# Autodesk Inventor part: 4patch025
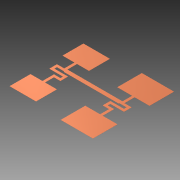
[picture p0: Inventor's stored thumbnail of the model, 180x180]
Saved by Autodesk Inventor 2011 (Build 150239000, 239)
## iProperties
Created: 2014-03
Part Number: 4patch025
Document SubType Name: Modeling
Designer: Evgeny
Density: 1 g/cm^3
Author: Evgeny
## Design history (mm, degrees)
sketch "Эскиз1"
  geometry: L1 (-64.5, 4.5)-(64.5, 4.5); L2 (64.5, -3)-(64.5, -4.5); L3 (64.5, -4.5)-(-64.5, -4.5); L4 (-64.5, -4.5)-(-64.5, -3); L5 (-70.5, 3)-(-72.9, 3); L6 (-81.5, -3)-(-64.5, -3); L7 (-70.5, 3)-(-70.5, 27); L8 (-64.5, 27)-(-64.5, 4.5); L9 (-72.9, 3)-(-87.5, 3); L10 (-87.5, 3)-(-87.5, -14); L11 (-81.5, -9)-(-81.5, -3); L12 (-81.5, -9)-(-49.5, -9); L13 (-49.5, -9)-(-49.5, -25); L14 (-55.5, -15)-(-87.5, -15); L15 (-87.5, -15)-(-87.5, -14); L16 (-55.5, -15)-(-55.5, -21); L17 (-49.5, -27)-(-49.5, -25); L18 (-49.5, -27)-(-64.5, -27); L19 (-70.5, -37)-(-70.5, -21); L20 (-70.5, -21)-(-55.5, -21); L21 (-70.5, -21)-(-57.4, -21); L22 (-64.5, -27)-(-64.5, -48); L23 (-70.5, -48)-(-70.5, -21); L24 (70.5, 3)-(87.5, 3); L25 (87.5, 3)-(87.5, -3); L26 (81.5, -3)-(64.5, -3); L27 (70.5, 3)-(70.5, 27); L28 (64.5, 27)-(64.5, 4.5); L29 (81.5, -3)-(81.5, -9); L30 (85.5, -15)-(87.5, -15); L31 (87.5, -15)-(87.5, -3); L32 (85.5, -15)-(55.5, -15); L33 (49.5, -15)-(49.5, -9); L34 (49.5, -9)-(81.5, -9); L35 (49.5, -9)-(55.5, -9); L36 (55.5, -15)-(55.5, -21); L37 (55.5, -27)-(49.5, -27); L38 (49.5, -27)-(49.5, -9); L39 (55.5, -27)-(64.5, -27); L40 (70.5, -27)-(70.5, -21); L41 (70.5, -21)-(55.5, -21); L42 (70.5, -21)-(65, -21); L43 (64.5, -27)-(64.5, -48); L44 (70.5, -48)-(70.5, -21); L45 (-98.5, 76)-(-36.5, 76); L46 (-36.5, 76)-(-36.5, 27); L47 (-98.5, 27)-(-98.5, 76); L48 (29.75, 84.5)-(105.25, 84.5); L49 (105.25, 84.5)-(105.25, 27); L50 (29.75, 27)-(29.75, 84.5); L51 (-98.5, -97)-(-36.5, -97); L52 (-36.5, -97)-(-36.5, -48); L53 (-98.5, -48)-(-98.5, -97); L54 (29.75, -105.5)-(105.25, -105.5); L55 (105.25, -105.5)-(105.25, -48); L56 (29.75, -48)-(29.75, -105.5); L57 (-36.5, 27)-(-64.5, 27); L58 (-70.5, 27)-(-98.5, 27); L59 (105.25, 27)-(70.5, 27); L60 (64.5, 27)-(29.75, 27); L61 (-36.5, -48)-(-64.5, -48); L62 (-70.5, -48)-(-98.5, -48); L63 (105.25, -48)-(70.5, -48); L64 (64.5, -48)-(29.75, -48); 1 further point
  constraints: 128 end point, 30 parallel, 15 horizontal, 14 perpendicular, 6 collinear
  dimensions: "d0" = 129 distance between parallel lines of L2 L4; "d1" = 64.5 distance from line of point (0, 0) L4; "d2" = 9 distance between parallel lines of L3 L1; "d3" = 4.5 distance from line of point (0, 0) L3; "d5" = 6 distance between parallel lines of L5 L6; "d7" = 6 distance between parallel lines of L7 L8; "d8" = 17 distance from line of L4.end L11; "d9" = 6 distance between parallel lines of L10 L11; "d10" = 6 distance between parallel lines of L12 L6; "d11" = 6 distance between parallel lines of L14 L12; "d12" = 15 distance between parallel lines of L17 L22; "d13" = 6 distance between parallel lines of L17 L16; "d14" = 6 distance between parallel lines of L18 L20; "d15" = 6 distance between parallel lines of L23 L22; "d18" = 64.5 distance from line of L22 point (0, 0); "d19" = 6 distance between parallel lines of L27 L28; "d20" = 17 distance between parallel lines of L29 L2; "d21" = 6 distance between parallel lines of L24 L26; "d22" = 6 distance between parallel lines of L31 L29; "d23" = 6 distance between parallel lines of L32 L34; "d24" = 6 distance between parallel lines of L44 L43; "d25" = 6 distance between parallel lines of L39 L41; "d26" = 6 distance between parallel lines of L38 L36; "d27" = 129 distance between parallel lines of L43 L22; "d28" = 15 distance between parallel lines of L38 L43; "d31" = 62 distance between parallel lines of L47 L46; "d33" = 75.5 distance between parallel lines of L49 L50; "d38" = 62 distance between parallel lines of L52 L53; "d40" = 75.5 distance between parallel lines of L55 L56; "d47" = 1.5 distance between parallel lines of L5 L1; "d48" = 1.5 distance between parallel lines of L24 L1; "d49" = 6 distance between parallel lines of L34 L26; "d50" = 129 distance between parallel lines of L28 L8; "d51" = 64.5 distance from line of L8 point (0, 0); "d52" = 49 distance between parallel lines of L58 L45; "d53" = 49 distance between parallel lines of L51 L62; "d54" = 57.5 distance between parallel lines of L48 L59; "d55" = 57.5 distance between parallel lines of L54 L63; "d56" = 28 distance between parallel lines of L46 L8; "d57" = 34.75 distance between parallel lines of L50 L28
extrude "Выдавливание1" new body sketch "Эскиз1" distance "d43" = 0.25; taper "d44" = 0 deg
node "Твердое тело1"
other parameters: "d32" = 49, "d34" = 57.5, "d37" = 49, "d39" = 57.5, "d45" = 33, "d46" = 33
